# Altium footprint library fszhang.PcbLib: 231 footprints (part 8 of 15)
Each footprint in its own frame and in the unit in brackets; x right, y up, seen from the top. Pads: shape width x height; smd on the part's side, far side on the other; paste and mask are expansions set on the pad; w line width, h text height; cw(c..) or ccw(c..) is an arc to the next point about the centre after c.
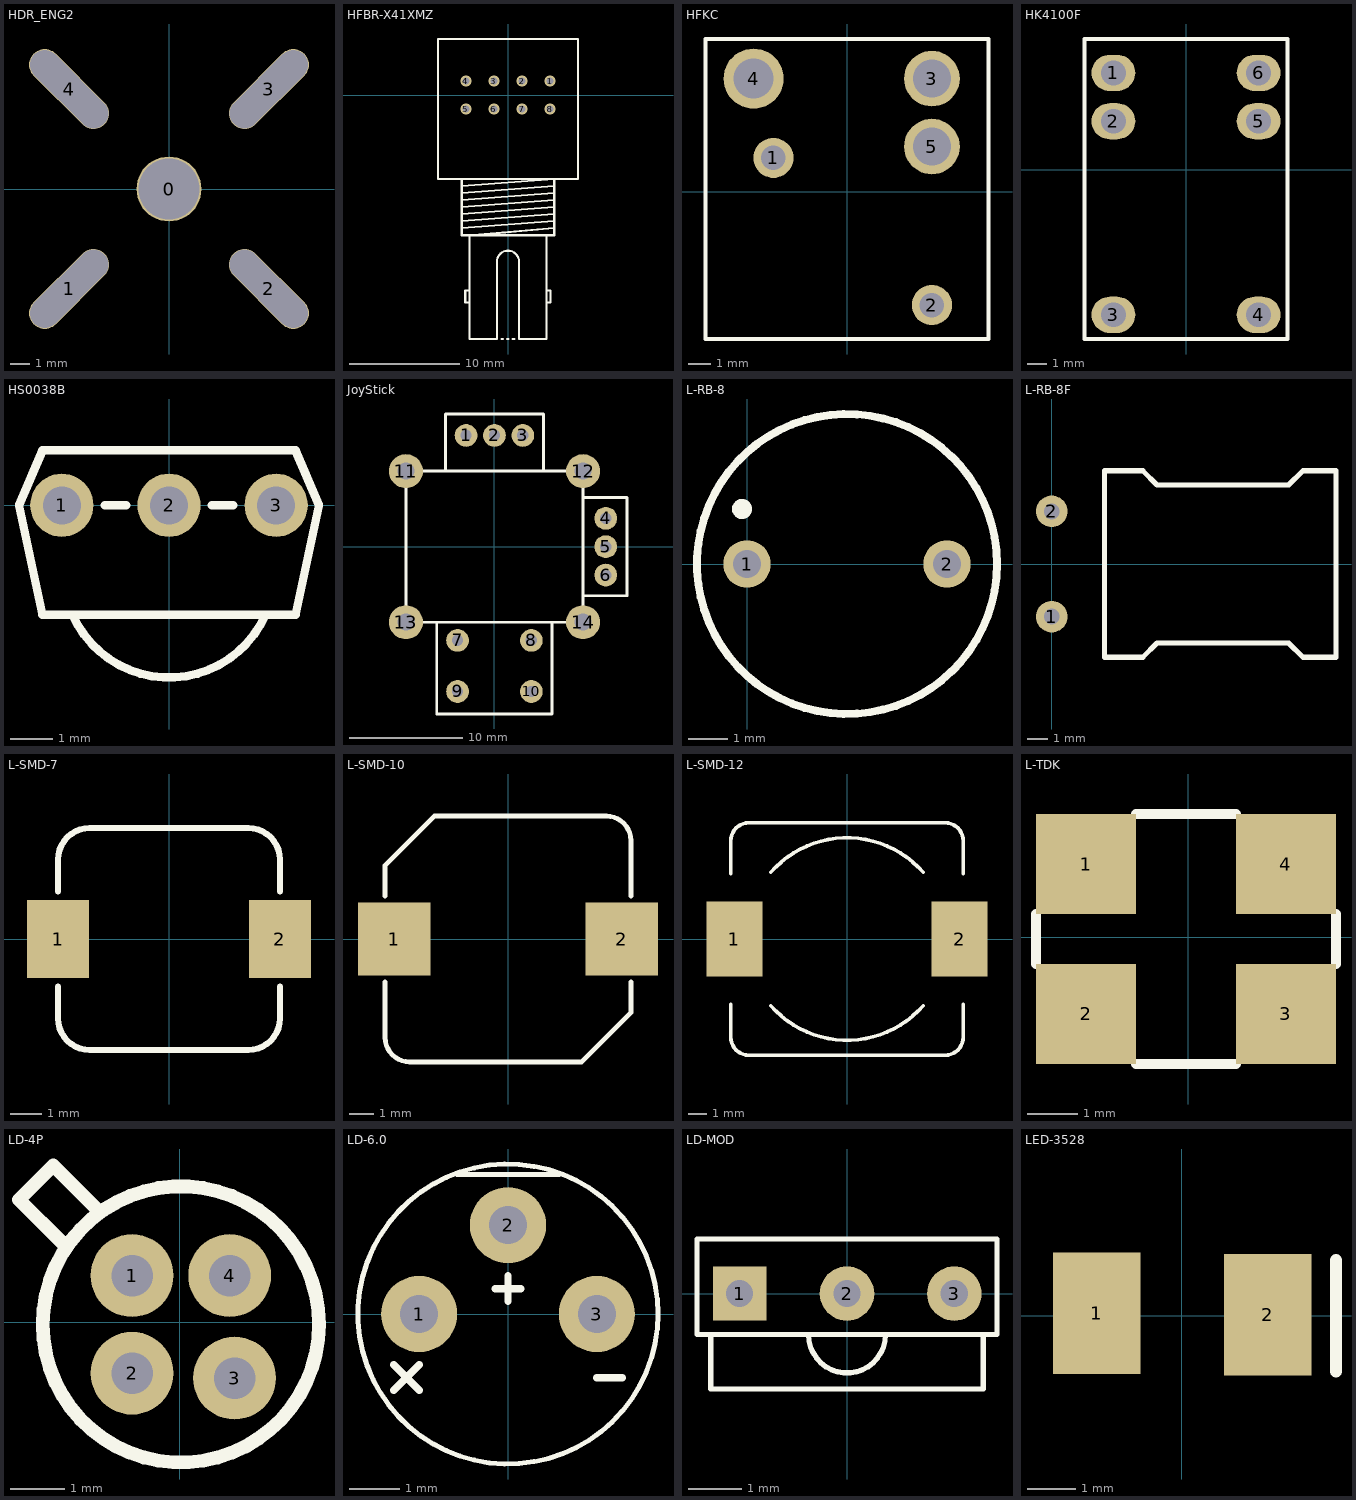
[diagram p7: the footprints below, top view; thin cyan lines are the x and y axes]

## HDR_ENG2 [mm] "舵机"
height 3
pads (5):
  round 3.3 hole 3.1: 0(0,0)
  oval 1.6x5.1 hole 1.5 slot 5 at 45 deg rot 135: 1(-5.08,-5.08) 3(5.08,5.08)
  oval 1.6x5.1 hole 1.5 slot 5 at 135 deg rot 45: 2(5.08,-5.08) 4(-5.08,5.08)

## HFBR-X41XMZ [mm]
height 10.2
pads (8):
  round 1 hole 0.6: 1(3.81,1.27) 2(1.27,1.27) 3(-1.27,1.27) 4(-3.81,1.27) 5(-3.81,-1.27) 6(-1.27,-1.27) 7(1.27,-1.27) 8(3.81,-1.27)
Top Overlay:
  lines w0.2: -4.2,-12.065 4.2,-11.43 ; -4.2,-11.43 4.2,-10.795 ; -4.2,-10.795 4.2,-10.16 ; -4.2,-10.16 4.2,-9.525 ; -4.2,-9.525 4.2,-8.89 ; -4.2,-8.89 4.191,-8.255 ; -4.191,-8.255 4.2,-7.62 ; -3.5,-18.82 -3.881,-18.82 -3.881,-17.72 -3.5,-17.72 ; -3.175,-12.72 4.2,-12.065 ; -0.579,-22.12 -0.452,-22.12 ; -0.071,-22.12 0.056,-22.12 ; 0.437,-22.12 0.564,-22.12 ; 1,-15.12 1,-22.12 3.5,-22.12 3.5,-12.72 -3.5,-12.72 -3.5,-22.12 -1,-22.12 -1,-15.12 cw(c0,-15.113) 1,-15.113 ; 3.5,-18.82 3.866,-18.82 3.866,-17.72 3.5,-17.72 ; 4.2,-7.62 4.2,-12.72 -4.2,-12.72 -4.2,-7.62 4.2,-7.62 ; -6.35,-7.62 6.35,-7.62 6.35,5.08 -6.35,5.08 -6.35,-7.62

## HFKC [mm] "继电器"
height 11.8
pads (5):
  round 1.8 hole 1.1: 1(-3.302,1.524) 2(3.81,-5.08)
  round 2.5 hole 1.7: 3(3.81,5.08) 5(3.81,2.032)
  round 2.7 hole 1.8: 4(-4.191,5.08)
Top Overlay:
  lines w0.2: -6.35,-6.604 6.35,-6.604 6.35,6.858 -6.35,6.858 -6.35,-6.604

## HK4100F [mm] "¼Ìµ"
height 11.8
pads (6):
  oval 2.3x1.9 hole 1.3: 1(-3.81,5.08) 2(-3.81,2.54) 3(-3.81,-7.62) 4(3.81,-7.62) 5(3.81,2.54) 6(3.81,5.08)
Top Overlay:
  lines w0.2: -5.334,-8.89 -5.334,6.858 5.334,6.858 5.334,-8.89 -5.334,-8.89
3D body: height 12, standoff 0, extent -5.334,-8.89 5.334,6.858

## HS0038B [mm] "红外接收头"
height 6.95
pads (3):
  round 1.5 hole 0.9: 1(-2.54,0) 2(0,0) 3(2.54,0)
Top Overlay:
  lines w0.2: -2.285,-2.599 ccw(c0,-1.584) 2.285,-2.599 ; -1.524,0 -1.016,0 ; 1.016,0 1.524,0 ; -3.556,0 -3,-2.6 3,-2.6 3.556,0 3,1.3 -3,1.3 -3.556,0

## JoyStick [mm] "Ä£Ä"
height 20
pads (14):
  round 2 hole 1: 1(-2.5,9.8) 2(0,9.8) 3(2.5,9.8) 4(9.8,2.5) 5(9.8,0) 6(9.8,-2.5) 7(-3.25,-8.25) 8(3.25,-8.25) 9(-3.25,-12.75) 10(3.25,-12.75)
  round 3 hole 1.5: 11(-7.8,6.65) 12(7.8,6.65) 13(-7.8,-6.65) 14(7.8,-6.65)
Top Overlay:
  lines w0.254: -5.08,-6.65 -5.08,-14.732 5.08,-14.732 5.08,-6.65 ; -4.318,6.65 -4.318,11.684 4.318,11.684 4.318,6.65 ; 7.8,-4.318 11.684,-4.318 11.684,4.318 7.8,4.318 ; -7.8,-6.65 7.8,-6.65 7.8,6.65 -7.8,6.65 -7.8,-6.65

## L-RB-8 [mm] "Inductor"
pads (2):
  round 1.2 hole 0.7: 1(0,0) 2(5.08,0)
Top Overlay:
  circle w0.2: c2.54,0 r3.81
  circle w0.254: c-0.127,1.397 r0.127

## L-RB-8F [mil] "ֱ?"
height 472.44
pads (2):
  round 60 hole 30: 1(0,-100) 2(0,100)
Top Overlay:
  lines w10: 100,-177.17 100,177.17 172.83,177.17 200,150 450,150 477.17,177.17 540,177.17 540,-177.17 477.17,-177.17 450,-150 200,-150 172.83,-177.17 100,-177.17

## L-SMD-7 [mm] "贴片电感7*7"
pads (2):
  rect 2x2.5 smd: 1(-3.556,0) 2(3.556,0)
Top Overlay:
  lines w0.2: -3.556,-1.524 -3.556,-2.54 ccw(c-2.54,-2.54) -2.54,-3.556 2.54,-3.556 ccw(c2.54,-2.54) 3.556,-2.54 3.556,-1.524 ; -3.556,1.524 -3.556,2.54 cw(c-2.54,2.54) -2.54,3.556 2.54,3.556 cw(c2.54,2.54) 3.556,2.54 3.556,1.524
3D body: height 4, standoff 0, extent -3.556,-3.556 3.556,3.556

## L-SMD-10 [mm] "贴片电感10*10"
pads (2):
  rect 3x3 smd: 1(-4.699,0) 2(4.699,0)
Top Overlay:
  lines w0.2: -5.08,-1.778 -5.08,-4.064 ccw(c-4.064,-4.064) -4.064,-5.08 3.048,-5.08 5.08,-3.048 5.08,-1.778 ; -5.08,1.778 -5.08,3.048 -3.048,5.08 4.064,5.08 cw(c4.064,4.064) 5.08,4.064 5.08,1.778
3D body: height 4, standoff 0, extent -5.08,-5.08 5.08,5.08

## L-SMD-12 [mm] "贴片电感12*12"
height 4
pads (2):
  rect 3x4 smd: 1(-6,0) 2(6,0)
Top Overlay:
  lines w0.2: -6.2,-3.475 -6.2,-5.23 ccw(c-5.23,-5.23) -5.23,-6.2 5.23,-6.2 ccw(c5.23,-5.23) 6.2,-5.23 6.2,-3.475 ; -6.2,3.475 -6.2,5.23 cw(c-5.23,5.23) -5.23,6.2 5.23,6.2 cw(c5.23,5.23) 6.2,5.23 6.2,3.475 ; -4.064,-3.556 ccw(c0,0) 4.064,-3.556 ; -4.064,3.556 cw(c0,0) 4.064,3.556
3D body: height 0.6, standoff 0, extent -6.207,-6.233 6.207,6.182
3D body: height 2.5, standoff 0.3, extent -5.273,-5.303 5.315,5.29

## L-TDK [mm]
height 10
pads (4):
  rect 2x2 smd: 1(-2.048,1.46) 2(-2.048,-1.54) 3(1.952,-1.54) 4(1.952,1.46)
Top Overlay:
  lines w0.2: -3.048,-0.54 -3.048,0.46 ; -1.048,-2.54 0.952,-2.54 ; -1.048,2.46 0.952,2.46 ; 2.952,-0.54 2.952,0.46

## LD-4P [mil]
pads (4):
  round 60 hole 30: 1(-34.71,33.93) 2(-34.71,-36.78) 3(39.54,-40.33) 4(35.98,33.92)
Top Overlay:
  circle w10: c0.64,-1.43 r100
  lines w9.84: -84.75,57.04 -116.57,88.86 -91.82,113.61 -60,81.79

## LD-6.0 [mil] "¼¤¹âÖ±¾"
height 511.81
pads (3):
  round 60 hole 30: 1(-70,0) 2(0,70) 3(70,0)
Top Overlay:
  circle w3.94: c0,0 r118.11
  lines w3.94: -40,110 40,110
  lines w5.91: -90,-60 -70,-40 ; -90,-40 -70,-60 ; -10,20 10,20 ; 0,10 0,30 ; 70,-50 90,-50

## LD-MOD [mm] "激光"
height 5
pads (3):
  rect 1x1 hole 0.5: 1(-2,0)
  round 1.016 hole 0.5: 2(0,0)
  round 1.016 hole 0.508: 3(2,0)
Top Overlay:
  lines w0.1: -2.54,-0.762 -2.54,-1.778 2.54,-1.778 2.54,-0.762 ; -0.718,-0.762 ccw(c0,-0.762) 0.718,-0.762 ; -2.794,-0.762 -2.794,1.016 2.794,1.016 2.794,-0.762 -2.794,-0.762

## LED-3528 [mm] "贴片二极管"
height 3
pads (2):
  rect 1.8x2.5 smd: 1(-1.753,0.052) 2(1.772,0.027)
Top Overlay:
  lines w0.254: 3.175,-1.143 3.175,1.143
